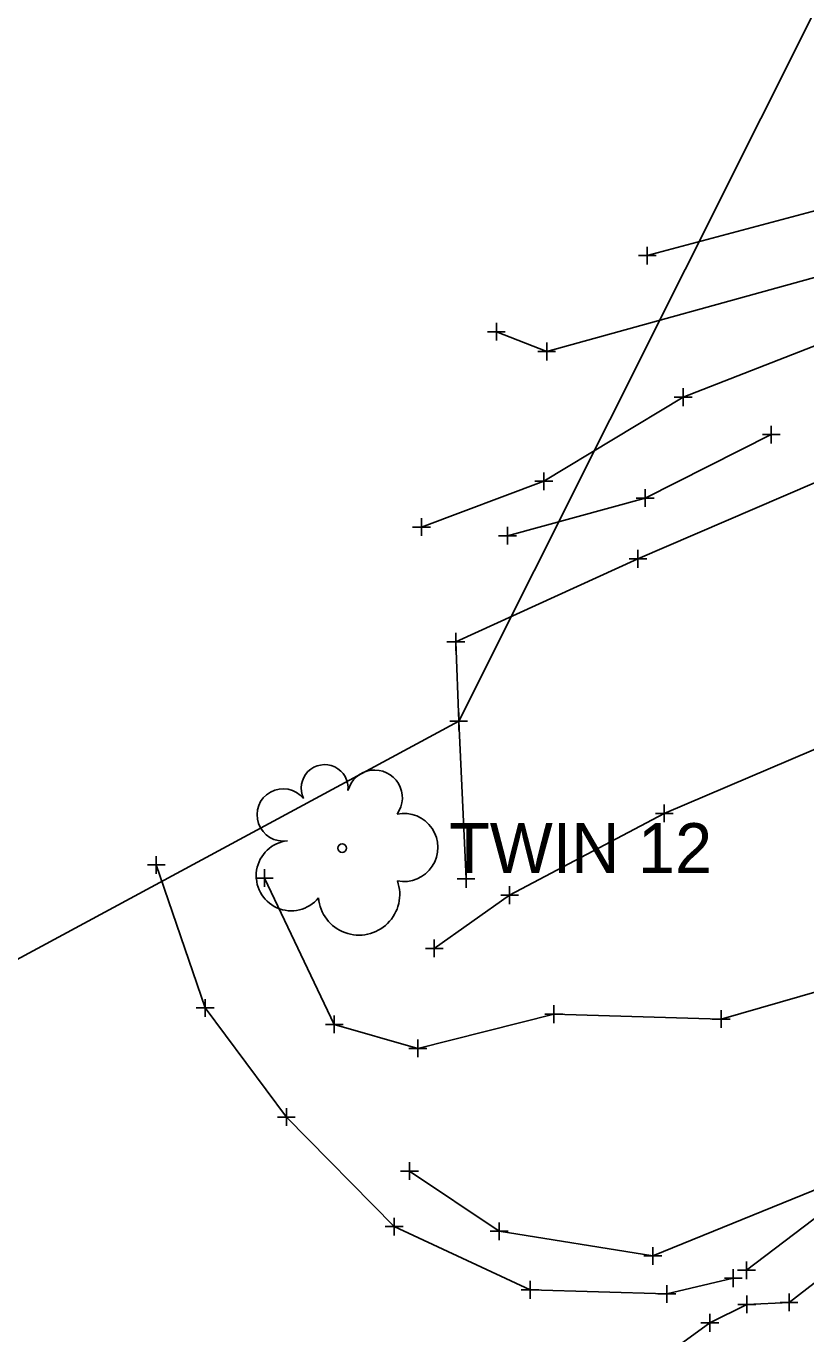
# Model space of a CAD drawing. Extents: x 2184635 to 2185378, y 369880 to 370486.
# Drawn here: x 2185024.5 to 2185068.3, y 370246.3 to 370319.8 of the extents above; entities that cross this region are included whole.
import ezdxf

# ---------------------------------------------------------------- set-up
doc = ezdxf.new("R2010")
doc.units = 0
for name, color, linetype in [('DR_X_Ditch', 7, 'Continuous'), ('GE_X_Alignment', 7, 'Continuous'), ('GE_X_Alignment_100_Distances', 7, 'Continuous'), ('PV_X_Driveway', 7, 'Continuous'), ('PV_X_Shoulder', 7, 'Continuous'), ('RD_X_GR_Lt', 7, 'Continuous'), ('RW_X_CL', 7, 'Continuous'), ('SV_X_Break_Lines', 7, 'Continuous'), ('SV_X_Terrain_Boundary', 7, 'Continuous'), ('VG_X_Text', 7, 'Continuous')]:
    doc.layers.add(name, color=color, linetype=linetype)

msp = doc.modelspace()

# ---------------------------------------------------------------- linework, layer by layer
at = {"layer": 'DR_X_Ditch'}
msp.add_lwpolyline([(2185097.066, 370309.962), (2185087.789, 370312.42), (2185079.038, 370309.308), (2185071.088, 370308.099), (2185069.431, 370305.844), (2185053.728, 370301.514), (2185050.899, 370302.622)], dxfattribs=at)
at = {"layer": 'GE_X_Alignment'}
msp.add_circle((2185042.243, 370273.623), 0.24, dxfattribs=at)
for centre, radius, start, end in [((2185041.26, 370276.991), 1.317, 354.0047, 205.97412), ((2185044.07, 370276.452), 1.553, 323.82996, 165.0376), ((2185038.934, 370275.487), 1.471, 39.06254, 279.54124), ((2185045.704, 370273.659), 1.915, 259.14531, 101.45961), ((2185039.39, 370272.074), 1.974, 96.17219, 320.57371), ((2185043.19, 370271.018), 2.284, 184.94757, 19.45715)]:
    msp.add_arc(centre, radius, start, end, dxfattribs=at)
at = {"layer": 'GE_X_Alignment_100_Distances'}
msp.add_lwpolyline([(2185064.938, 370249.915), (2185090.369, 370269.214), (2185130.506, 370301.429), (2185168.462, 370331.991), (2185206.748, 370363.667), (2185245.64, 370395.454)], dxfattribs=at)
at = {"layer": 'PV_X_Driveway'}
msp.add_lwpolyline([(2185031.808, 370272.676), (2185034.555, 370264.644), (2185039.113, 370258.521), (2185045.163, 370252.364), (2185052.789, 370248.818), (2185060.472, 370248.582), (2185064.197, 370249.468)], dxfattribs=at)
at = {"layer": 'PV_X_Shoulder'}
msp.add_lwpolyline([(2184660.616, 369924.653), (2184701.177, 369956.993), (2184739.308, 369987.689), (2184778.66, 370019.08), (2184817.145, 370050.202), (2184856.424, 370081.402), (2184897.962, 370114.276), (2184936.317, 370143.726), (2184975.811, 370174.815), (2184986.608, 370184.308), (2184994.082, 370192.548), (2185011.043, 370206.648), (2185033.171, 370224.287), (2185051.814, 370238.9), (2185062.885, 370246.964), (2185064.956, 370248.001), (2185067.328, 370248.113), (2185092.06, 370267.243), (2185132.002, 370299.513), (2185169.971, 370330.255), (2185208.837, 370361.607), (2185247.242, 370392.983)], dxfattribs=at)
at = {"layer": 'RD_X_GR_Lt'}
msp.add_lwpolyline([(2185046.02, 370255.484), (2185051.058, 370252.105), (2185059.685, 370250.72), (2185069.217, 370254.599), (2185088.99, 370270.332), (2185128.498, 370302.326), (2185166.722, 370333.304), (2185205.522, 370364.756), (2185244.075, 370396.55), (2185351.751, 370485.271)], dxfattribs=at)
at = {"layer": 'RW_X_CL'}
for p, q in [((2185059.374, 370307.395), (2185059.374, 370306.395)), ((2185058.874, 370306.895), (2185059.874, 370306.895)), ((2185059.374, 370306.895), (2185059.374, 370306.895)), ((2185050.899, 370303.122), (2185050.899, 370302.122)), ((2185050.399, 370302.622), (2185051.399, 370302.622)), ((2185050.899, 370302.622), (2185050.899, 370302.622)), ((2185053.728, 370302.014), (2185053.728, 370301.014)), ((2185053.228, 370301.514), (2185054.228, 370301.514)), ((2185053.728, 370301.514), (2185053.728, 370301.514)), ((2185061.386, 370299.445), (2185061.386, 370298.445)), ((2185060.886, 370298.945), (2185061.886, 370298.945)), ((2185061.386, 370298.945), (2185061.386, 370298.945)), ((2185065.835, 370296.845), (2185066.835, 370296.845)), ((2185066.335, 370297.345), (2185066.335, 370296.345)), ((2185066.335, 370296.845), (2185066.335, 370296.845)), ((2185053.561, 370294.722), (2185053.561, 370293.722)), ((2185053.061, 370294.222), (2185054.061, 370294.222)), ((2185053.561, 370294.222), (2185053.561, 370294.222)), ((2185058.753, 370293.278), (2185059.753, 370293.278)), ((2185059.253, 370293.778), (2185059.253, 370292.778)), ((2185059.253, 370293.278), (2185059.253, 370293.278)), ((2185046.2, 370291.65), (2185047.2, 370291.65)), ((2185046.7, 370292.15), (2185046.7, 370291.15)), ((2185046.7, 370291.65), (2185046.7, 370291.65)), ((2185051.523, 370291.663), (2185051.523, 370290.663)), ((2185051.023, 370291.163), (2185052.023, 370291.163)), ((2185051.523, 370291.163), (2185051.523, 370291.163)), ((2185058.85, 370290.368), (2185058.85, 370289.368)), ((2185058.35, 370289.868), (2185059.35, 370289.868)), ((2185058.85, 370289.868), (2185058.85, 370289.868)), ((2185048.121, 370285.205), (2185049.121, 370285.205)), ((2185048.621, 370285.705), (2185048.621, 370284.705)), ((2185048.621, 370285.205), (2185048.621, 370285.205)), ((2185048.288, 370280.746), (2185049.288, 370280.746)), ((2185048.788, 370281.246), (2185048.788, 370280.246)), ((2185048.788, 370280.746), (2185048.788, 370280.746)), ((2185059.825, 370275.571), (2185060.825, 370275.571)), ((2185060.325, 370276.071), (2185060.325, 370275.071)), ((2185060.325, 370275.571), (2185060.325, 370275.571)), ((2185031.308, 370272.676), (2185032.308, 370272.676)), ((2185031.808, 370273.176), (2185031.808, 370272.176)), ((2185031.808, 370272.676), (2185031.808, 370272.676)), ((2185037.374, 370271.942), (2185038.374, 370271.942)), ((2185037.874, 370272.442), (2185037.874, 370271.442)), ((2185037.874, 370271.942), (2185037.874, 370271.942)), ((2185048.698, 370271.897), (2185049.698, 370271.897)), ((2185049.198, 370272.397), (2185049.198, 370271.397)), ((2185049.198, 370271.897), (2185049.198, 370271.897)), ((2185051.642, 370271.482), (2185051.642, 370270.482)), ((2185051.142, 370270.982), (2185052.142, 370270.982)), ((2185051.642, 370270.982), (2185051.642, 370270.982)), ((2185047.413, 370268.493), (2185047.413, 370267.493)), ((2185046.913, 370267.993), (2185047.913, 370267.993)), ((2185047.413, 370267.993), (2185047.413, 370267.993)), ((2185034.055, 370264.644), (2185035.055, 370264.644)), ((2185034.555, 370265.144), (2185034.555, 370264.144)), ((2185034.555, 370264.644), (2185034.555, 370264.644)), ((2185054.122, 370264.796), (2185054.122, 370263.796)), ((2185063.517, 370264.524), (2185063.517, 370263.524)), ((2185041.3, 370263.72), (2185042.3, 370263.72)), ((2185041.8, 370264.22), (2185041.8, 370263.22)), ((2185041.8, 370263.72), (2185041.8, 370263.72)), ((2185053.622, 370264.296), (2185054.622, 370264.296)), ((2185054.122, 370264.296), (2185054.122, 370264.296)), ((2185063.017, 370264.024), (2185064.017, 370264.024)), ((2185063.517, 370264.024), (2185063.517, 370264.024)), ((2185045.994, 370262.377), (2185046.994, 370262.377)), ((2185046.494, 370262.877), (2185046.494, 370261.877)), ((2185046.494, 370262.377), (2185046.494, 370262.377)), ((2185039.113, 370259.021), (2185039.113, 370258.021)), ((2185038.613, 370258.521), (2185039.613, 370258.521)), ((2185039.113, 370258.521), (2185039.113, 370258.521)), ((2185046.02, 370255.984), (2185046.02, 370254.984)), ((2185045.52, 370255.484), (2185046.52, 370255.484)), ((2185046.02, 370255.484), (2185046.02, 370255.484)), ((2185045.163, 370252.864), (2185045.163, 370251.864)), ((2185044.663, 370252.364), (2185045.663, 370252.364)), ((2185045.163, 370252.364), (2185045.163, 370252.364)), ((2185050.558, 370252.105), (2185051.558, 370252.105)), ((2185051.058, 370252.605), (2185051.058, 370251.605)), ((2185051.058, 370252.105), (2185051.058, 370252.105)), ((2185059.185, 370250.72), (2185060.185, 370250.72)), ((2185059.685, 370251.22), (2185059.685, 370250.22)), ((2185059.685, 370250.72), (2185059.685, 370250.72)), ((2185064.197, 370249.968), (2185064.197, 370248.968)), ((2185064.438, 370249.915), (2185065.438, 370249.915)), ((2185064.938, 370250.415), (2185064.938, 370249.415)), ((2185064.938, 370249.915), (2185064.938, 370249.915)), ((2185052.789, 370249.318), (2185052.789, 370248.318)), ((2185060.472, 370249.082), (2185060.472, 370248.082)), ((2185063.697, 370249.468), (2185064.697, 370249.468)), ((2185064.197, 370249.468), (2185064.197, 370249.468)), ((2185052.289, 370248.818), (2185053.289, 370248.818)), ((2185052.789, 370248.818), (2185052.789, 370248.818)), ((2185059.972, 370248.582), (2185060.972, 370248.582)), ((2185060.472, 370248.582), (2185060.472, 370248.582)), ((2185064.956, 370248.501), (2185064.956, 370247.501)), ((2185067.328, 370248.613), (2185067.328, 370247.613)), ((2185064.456, 370248.001), (2185065.456, 370248.001)), ((2185064.956, 370248.001), (2185064.956, 370248.001)), ((2185066.828, 370248.113), (2185067.828, 370248.113)), ((2185067.328, 370248.113), (2185067.328, 370248.113)), ((2185062.385, 370246.964), (2185063.385, 370246.964)), ((2185062.885, 370247.464), (2185062.885, 370246.464)), ((2185062.885, 370246.964), (2185062.885, 370246.964))]:
    msp.add_line(p, q, dxfattribs=at)
at = {"layer": 'SV_X_Break_Lines'}
for points in [[(2185238.668, 370405.318), (2185202.581, 370371.499), (2185173.504, 370347.593), (2185162.544, 370339.328), (2185125.289, 370312.922), (2185086.214, 370274.11), (2185072.344, 370266.561), (2185063.517, 370264.024), (2185054.122, 370264.296), (2185046.494, 370262.377), (2185041.8, 370263.72), (2185037.874, 370271.942)], [(2185059.374, 370306.895), (2185071.162, 370310.043), (2185080.719, 370314.696), (2185090.033, 370315.721), (2185093.593, 370314.581)], [(2185092.748, 370307.972), (2185085.782, 370309.219), (2185075.536, 370304.474), (2185061.386, 370298.945), (2185053.561, 370294.222), (2185046.7, 370291.65)], [(2185103.101, 370305.456), (2185104.93, 370304.033), (2185100.103, 370298.021), (2185090.668, 370293.19), (2185074.547, 370281.628), (2185060.325, 370275.571), (2185051.642, 370270.982), (2185047.413, 370267.993)], [(2185049.198, 370271.897), (2185048.788, 370280.746), (2185048.621, 370285.205), (2185058.85, 370289.868), (2185070.374, 370294.831), (2185087.815, 370299.755), (2185096.348, 370301.093)], [(2185051.523, 370291.163), (2185059.253, 370293.278), (2185066.335, 370296.845)]]:
    msp.add_lwpolyline(points, dxfattribs=at)
at = {"layer": 'SV_X_Terrain_Boundary'}
msp.add_lwpolyline([(2184974.137, 370097.077), (2185033.603, 370139.079), (2185056.498, 370157.156), (2185084.693, 370178.208), (2185162.576, 370240.184), (2185199.27, 370262.443), (2185215.204, 370306.943), (2185268.576, 370364.897), (2185258.835, 370377.241), (2185248.181, 370392.045), (2185238.668, 370405.318), (2185197.578, 370376.275), (2185164.413, 370344.459), (2185149.44, 370353.437), (2185069.982, 370323.057), (2185048.788, 370280.746), (2184981.838, 370244.628)], dxfattribs=at)

# ---------------------------------------------------------------- texts
at = {"layer": 'VG_X_Text'}
msp.add_text('TWIN 12', height=2.8, dxfattribs=at).set_placement((2185048.243, 370272.223))

doc.saveas('drawing.dxf')
